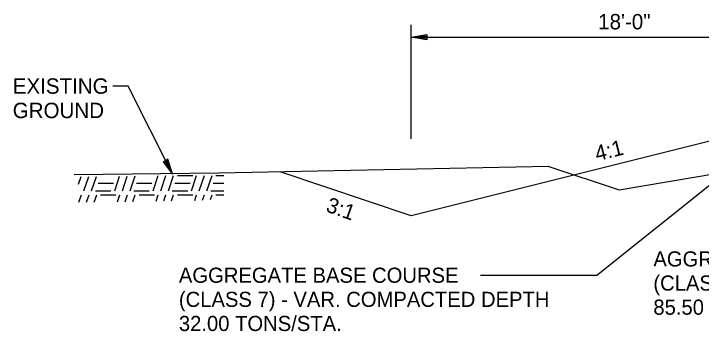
# Model space of a CAD drawing. Extents: x 1461570 to 1461697, y 1686711 to 1686957.
# Drawn here: x 1461572.73 to 1461599.57, y 1686909.96 to 1686922.34 of the extents above; entities that cross this region are included whole.
import ezdxf

# ---------------------------------------------------------------- set-up
doc = ezdxf.new("R2010")
doc.units = 0
for name, color, linetype in [('10', 7, 'Continuous'), ('19', 7, 'Continuous'), ('20', 7, 'Continuous'), ('42', 7, 'Continuous'), ('R_Draft', 7, 'Continuous'), ('R_Prop Surface', 7, 'Continuous')]:
    doc.layers.add(name, color=color, linetype=linetype)

msp = doc.modelspace()

# ---------------------------------------------------------------- linework, layer by layer
at = {"layer": '19'}
for p, q in [((1461595.484, 1686912.149), (1461602.242, 1686917.535)), ((1461588.246, 1686914.464), (1461583.124, 1686916.171)), ((1461590.949, 1686912.149), (1461595.484, 1686912.149))]:
    msp.add_line(p, q, dxfattribs=at)
at = {"layer": '20'}
for p, q in [((1461588.246, 1686917.465), (1461588.246, 1686921.9)), ((1461588.246, 1686921.428), (1461588.846, 1686921.533)), ((1461588.406, 1686921.443), (1461588.846, 1686921.478)), ((1461588.846, 1686921.533), (1461588.846, 1686921.323)), ((1461588.846, 1686921.323), (1461588.246, 1686921.428)), ((1461588.846, 1686921.373), (1461588.406, 1686921.413)), ((1461578.745, 1686916.663), (1461578.558, 1686916.569)), ((1461578.862, 1686916.23), (1461578.696, 1686916.639)), ((1461578.921, 1686916.08), (1461578.745, 1686916.663)), ((1461578.558, 1686916.569), (1461578.921, 1686916.08)), ((1461578.602, 1686916.591), (1461578.836, 1686916.216))]:
    msp.add_line(p, q, dxfattribs=at)
msp.add_lwpolyline([(1461578.921, 1686916.08), (1461577.191, 1686919.519), (1461576.591, 1686919.519)], dxfattribs=at)
at = {"layer": '42'}
for p, q in [((1461588.246, 1686921.428), (1461606.246, 1686921.428)), ((1461575.254, 1686915.692), (1461575.356, 1686915.998)), ((1461575.467, 1686915.431), (1461575.655, 1686915.996)), ((1461575.767, 1686915.431), (1461575.954, 1686915.993)), ((1461576.667, 1686915.431), (1461576.857, 1686916.003)), ((1461576.967, 1686915.431), (1461577.159, 1686916.009)), ((1461577.267, 1686915.431), (1461577.462, 1686916.016)), ((1461578.167, 1686915.431), (1461578.367, 1686916.031)), ((1461578.467, 1686915.431), (1461578.667, 1686916.031)), ((1461578.767, 1686915.431), (1461578.967, 1686916.031)), ((1461579.117, 1686916.031), (1461579.717, 1686916.031)), ((1461579.667, 1686915.431), (1461579.867, 1686916.031)), ((1461579.967, 1686915.431), (1461580.167, 1686916.031)), ((1461580.267, 1686915.431), (1461580.467, 1686916.031)), ((1461580.617, 1686916.031), (1461580.927, 1686916.031)), ((1461576.017, 1686915.731), (1461576.617, 1686915.731)), ((1461577.517, 1686915.731), (1461578.117, 1686915.731)), ((1461579.017, 1686915.731), (1461579.617, 1686915.731)), ((1461580.517, 1686915.731), (1461580.927, 1686915.731)), ((1461575.917, 1686915.431), (1461576.517, 1686915.431)), ((1461577.417, 1686915.431), (1461578.017, 1686915.431)), ((1461578.917, 1686915.431), (1461579.517, 1686915.431)), ((1461580.417, 1686915.431), (1461580.927, 1686915.431)), ((1461575.273, 1686914.998), (1461575.367, 1686915.281)), ((1461575.572, 1686914.996), (1461575.667, 1686915.281)), ((1461575.871, 1686914.994), (1461575.967, 1686915.281)), ((1461576.117, 1686915.281), (1461576.717, 1686915.281)), ((1461576.773, 1686915.001), (1461576.867, 1686915.281)), ((1461577.076, 1686915.008), (1461577.167, 1686915.281)), ((1461577.378, 1686915.014), (1461577.467, 1686915.281)), ((1461577.617, 1686915.281), (1461578.167, 1686915.281)), ((1461578.167, 1686915.281), (1461578.217, 1686915.281)), ((1461578.284, 1686915.033), (1461578.367, 1686915.281)), ((1461578.586, 1686915.039), (1461578.667, 1686915.281)), ((1461578.888, 1686915.045), (1461578.967, 1686915.281)), ((1461579.117, 1686915.281), (1461579.717, 1686915.281)), ((1461579.794, 1686915.064), (1461579.867, 1686915.281)), ((1461580.098, 1686915.074), (1461580.167, 1686915.281)), ((1461580.404, 1686915.092), (1461580.467, 1686915.281)), ((1461580.617, 1686915.281), (1461580.927, 1686915.281))]:
    msp.add_line(p, q, dxfattribs=at)
at = {"layer": 'R_Draft'}
for p, q in [((1461596.367, 1686915.478), (1461605.746, 1686917.041)), ((1461593.619, 1686916.388), (1461596.367, 1686915.478))]:
    msp.add_line(p, q, dxfattribs=at)
msp.add_lwpolyline([(1461593.619, 1686916.388), (1461580.727, 1686916.121), (1461575.084, 1686916.064)], dxfattribs=at)
at = {"layer": 'R_Prop Surface'}
msp.add_line((1461604.246, 1686918.464), (1461588.246, 1686914.464), dxfattribs=at)

# ---------------------------------------------------------------- texts
at = {"layer": '10'}
for s, p in [('EXISTING', (1461572.686, 1686919.219)), ('GROUND', (1461572.686, 1686918.269))]:
    msp.add_text(s, height=0.6, dxfattribs=at).set_placement(p)
at = {"layer": '19'}
for s, height, rotation, p in [('18\'-0"', 0.6, 360, (1461595.541, 1686921.728)), ('4:1', 0.6, 14.0362, (1461595.496, 1686916.586)), ('3:1', 0.6, 340.4943, (1461584.874, 1686914.641)), ('AGGREGATE BASE COURSE', 0.59001, 360, (1461597.696, 1686912.486)), ('AGGREGATE BASE COURSE', 0.59001, 360, (1461579.173, 1686911.851)), ('(CLASS 7) - 6" COMPACTED DEPTH', 0.59001, 360, (1461597.696, 1686911.546)), ('(CLASS 7) - VAR. COMPACTED DEPTH', 0.59001, 360, (1461579.173, 1686910.911)), ('85.50 TONS/STA.', 0.59001, 360, (1461597.696, 1686910.606)), ('32.00 TONS/STA.', 0.59001, 360, (1461579.173, 1686909.971))]:
    msp.add_text(s, height=height, rotation=rotation, dxfattribs=at).set_placement(p)

doc.saveas('drawing.dxf')
